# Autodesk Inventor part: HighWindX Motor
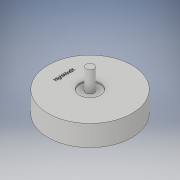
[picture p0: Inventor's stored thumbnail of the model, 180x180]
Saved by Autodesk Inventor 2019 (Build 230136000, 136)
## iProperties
Created: 2018-12
Part Number: HighWindX Motor
Material: Generic
Document SubType Name: Modeling
Designer: Patel Family
Density: 1 g/cm^3
Appearance: Default
Author: Patel Family
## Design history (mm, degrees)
sketch "Sketch1"
  geometry: C1 r 10 at (0, 0); 1 further point
  constraints: 1 centre point, 1 coincident
  dimensions: "d0" = 20 diameter of C1
extrude "Extrusion1" new body sketch "Sketch1" distance "d1" = 5; taper "d2" = 0 deg
sketch "Sketch2"
  geometry: C1 r 2.5 at (0, 0); 1 further point
  constraints: 1 centre point, 1 coincident
  dimensions: "d3" = 5 diameter of C1
extrude "Extrusion2" cut sketch "Sketch2" distance "d4" = 0.3; taper "d5" = 0 deg
sketch "Sketch3"
  geometry: C1 r 0.95 at (0, 0); 1 further point
  constraints: 1 centre point, 1 coincident
  dimensions: "d6" = 1.9 diameter of C1
extrude "Extrusion3" join sketch "Sketch3" distance "d7" = 5; taper "d8" = 0 deg
sketch "Sketch4"
  geometry: L1 (-6.493, -2.405)-(-6.493, 2.25); L2 (-6.493, 2.25)-(-5.563, 2.25); L3 (-5.563, 2.25)-(-5.563, -2.405); L4 (-5.563, -2.405)-(-6.493, -2.405); 1 further point
  constraints: 2 other
emboss "Emboss1" sketch "Sketch4" dims "d9" = 0.5, "d10" = 0
body "Solid1"
